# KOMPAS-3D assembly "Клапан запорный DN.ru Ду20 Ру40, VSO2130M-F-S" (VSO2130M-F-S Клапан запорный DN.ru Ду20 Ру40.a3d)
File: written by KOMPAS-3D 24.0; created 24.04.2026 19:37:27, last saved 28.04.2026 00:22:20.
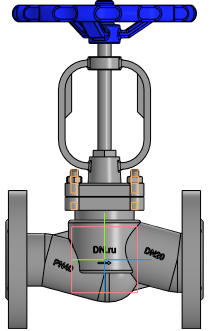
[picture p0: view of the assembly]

Document properties: Автор: DN.ru; Полное имя файла: C:\Работа\ГОТОВЫЕ ИСХОДНИКИ\VSO2130M-F-S Клапан запорный сальниковый DN.ru Ду15-100 Ру40\исходные материалы\DN20\VSO2130M-F-S Клапан запорный DN.ru Ду20 Ру40.a3d

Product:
- Component [detail]: Корпус  | qty 1  | pos. 1  | Масса: 6.9; Автор: R2D2; source file: Korpus.m3d
- Component [detail]: Деталь  | qty 1  | pos. 2  | Масса: 0.512593; Автор: mrdid; source file: rama.m3d
- Component [detail]: Деталь2  | qty 1  | pos. 3  | Масса: 0.594157; Автор: R2D2; additional columns: Типовые; source file: shturval.m3d
- Component [standard]: Шпилька М6-6gx25 ГОСТ 22032-76  | qty 4  | Масса: 0.005789; Раздел спецификации: Стандартные изделия; Рассекать на разрезах: no
- Component [standard]: Гайка М6-6H ГОСТ 5915-70  | qty 4  | Масса: 0.002573; Раздел спецификации: Стандартные изделия; Рассекать на разрезах: no
- Part/product: Клапан запорный DN.ru Ду20 Ру40  | designation VSO2130M-F-S
    Масса: 4.5
    Раздел спецификации: Прочие изделия
    Примечание: D090-01980

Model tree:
1. Контекстная связь:1  (with: Контекстная связь (Деталь):1)  (labels: Грань.Твердое тело1)
2. Контекстная связь:2  (with: Смещенная плоскость:4, Контекстная связь (Деталь):2)  (labels: Грань.Твердое тело1)
3. Контекстная связь:3  (with: Контекстная связь (Корпус):3)
4. Контекстная связь:4  (with: Эскиз:2, Ребро.Элемент выдавливания:14, Контекстная связь (Деталь):4)
5. Контекстная связь:5  (with: Контекстная связь (Деталь):5)
6. Массив по концентрической сетке:1  (with: Грань.Элемент выдавливания:1, Грань.Элемент выдавливания:15, Грань.Элемент выдавливания:3, Грань.Элемент выдавливания:2, Грань.Элемент выдавливания:16, Грань.Элемент выдавливания:14)  (labels: Грань.Твердое тело1)  (4 pattern instances)
     Шаг 2 = 360; Угол = 9

Referenced files in C:\Работа\ГОТОВЫЕ ИСХОДНИКИ\VSO2130M-F-S Клапан запорный сальниковый DN.ru Ду15-100 Ру40\исходные материалы\DN20\: Korpus.m3d, rama.m3d, shturval.m3d
Referenced files in C:\Program Files\ASCON\KOMPAS-3D v24\Libs\PolynomLib\DATA\vault\Methods\Kompas\3D\: PLib_Stud_1_900.m3d, PLib_Nut_OST92_900.m3d
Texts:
  BOSimple***PART:e489ae6d-d315-b2e9-dd59-4407119351be***SHORTLOC:Root±30±20±10±120±10±20[Нет;Без покрытия;Без указания материала;-;6;25;1;1]
  Крепежное изделие ГОСТ
  BOSimple***PART:832b7c99-94b5-75d7-382c-73b3a2f1c6df***SHORTLOC:Root±30±10±20±©{}110±10±50±60[Нет;Без покрытия;Без указания материала;-;6;1;10]
  Программные изделия  и базы данных
  VSO2130M-F-S
  Деталь2 Деталь2
  Шпилька М6-6gx25 ГОСТ 22032-76 (1)
  cut1
  Гайка М6-6H ГОСТ 5915-70 (1)
  bcut1
  hole1
  hcut1
  hole2
  Шпилька М6-6gx25 ГОСТ 22032-76 (2)
  Гайка М6-6H ГОСТ 5915-70 (2)
  Шпилька М6-6gx25 ГОСТ 22032-76 (3)
  Гайка М6-6H ГОСТ 5915-70 (3)
  Шпилька М6-6gx25 ГОСТ 22032-76 (4)
  Гайка М6-6H ГОСТ 5915-70 (4)
  Plane. Начало координат
  Плоскость ZX.Начало координат
  Плоскость XY.Начало координат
